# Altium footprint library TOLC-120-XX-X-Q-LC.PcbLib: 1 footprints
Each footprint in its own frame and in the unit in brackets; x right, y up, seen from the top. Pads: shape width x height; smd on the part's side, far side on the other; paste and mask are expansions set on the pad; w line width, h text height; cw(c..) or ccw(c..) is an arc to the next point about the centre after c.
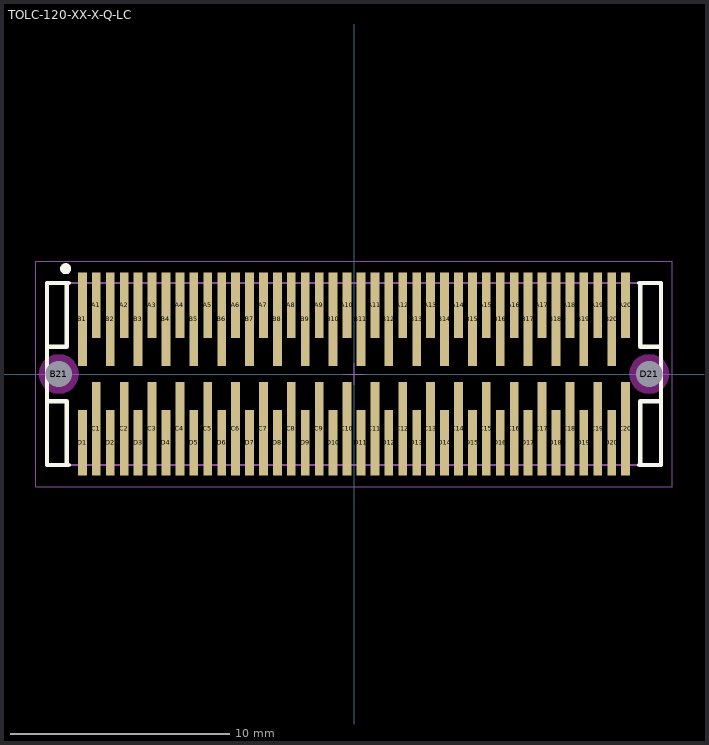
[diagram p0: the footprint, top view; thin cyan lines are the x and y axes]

## TOLC-120-XX-X-Q-LC [mm] "1.27mm pitch, 80 pin, terminal strip; 4 rows, w/locking clips, SMT"
height 5.59
pads (82):
  rect 0.4x3 smd mask+0: A1(-11.747,3.135) A2(-10.477,3.135) A3(-9.207,3.135) A4(-7.938,3.135) A5(-6.667,3.135) A6(-5.397,3.135) A7(-4.127,3.135) A8(-2.857,3.135) A9(-1.587,3.135) A10(-0.318,3.135) A11(0.953,3.135) A12(2.222,3.135) A13(3.492,3.135) A14(4.763,3.135) A15(6.032,3.135) A16(7.302,3.135) A17(8.572,3.135) A18(9.842,3.135) A19(11.112,3.135) A20(12.383,3.135) D1(-12.383,-3.135) D2(-11.112,-3.135) D3(-9.842,-3.135) D4(-8.572,-3.135) D5(-7.302,-3.135) D6(-6.032,-3.135) D7(-4.763,-3.135) D8(-3.492,-3.135) D9(-2.222,-3.135) D10(-0.953,-3.135) D11(0.318,-3.135) D12(1.587,-3.135) D13(2.857,-3.135) D14(4.127,-3.135) D15(5.397,-3.135) D16(6.667,-3.135) D17(7.938,-3.135) D18(9.207,-3.135) D19(10.477,-3.135) D20(11.747,-3.135)
  rect 0.4x4.25 smd mask+0: B1(-12.383,2.5) B2(-11.112,2.5) B3(-9.842,2.5) B4(-8.572,2.5) B5(-7.302,2.5) B6(-6.032,2.5) B7(-4.763,2.5) B8(-3.492,2.5) B9(-2.222,2.5) B10(-0.953,2.5) B11(0.318,2.5) B12(1.587,2.5) B13(2.857,2.5) B14(4.127,2.5) B15(5.397,2.5) B16(6.667,2.5) B17(7.938,2.5) B18(9.207,2.5) B19(10.477,2.5) B20(11.747,2.5) C1(-11.747,-2.5) C2(-10.477,-2.5) C3(-9.207,-2.5) C4(-7.938,-2.5) C5(-6.667,-2.5) C6(-5.397,-2.5) C7(-4.127,-2.5) C8(-2.857,-2.5) C9(-1.587,-2.5) C10(-0.318,-2.5) C11(0.953,-2.5) C12(2.222,-2.5) C13(3.492,-2.5) C14(4.763,-2.5) C15(6.032,-2.5) C16(7.302,-2.5) C17(8.572,-2.5) C18(9.842,-2.5) C19(11.112,-2.5) C20(12.383,-2.5)
  round 1 hole 1.2 unplated mask+0: B21(-13.462,0) D21(13.462,0)
Top Overlay:
  circle w0.25: c-13.15,4.8 r0.125
  lines w0.2: -14,-1.25 -13.1,-1.25 -13.1,-4.15 ; -14,1.25 -13.1,1.25 -13.1,4.15 ; -13,-4.15 -14,-4.15 -14,4.15 -13,4.15 ; 13,-4.15 14,-4.15 14,4.15 13,4.15 ; 13.05,-4.15 13.05,-1.25 13.95,-1.25 ; 13.05,4.15 13.05,1.25 13.95,1.25
Keep-Out Layer:
  pour cut-out: -12.554,0 -12.585,0.235 -12.676,0.454 -12.82,0.642 -13.008,0.786 -13.227,0.877 -13.462,0.908 -13.697,0.877 -13.916,0.786 -14.104,0.642 -14.248,0.454 -14.339,0.235 -14.37,0 -14.339,-0.235 -14.248,-0.454 -14.104,-0.642 -13.916,-0.786 -13.697,-0.877 -13.462,-0.908 -13.227,-0.877 -13.008,-0.786 -12.82,-0.642 -12.676,-0.454 -12.585,-0.235
  pour cut-out: 14.37,0 14.339,0.235 14.248,0.454 14.104,0.642 13.916,0.786 13.697,0.877 13.462,0.908 13.227,0.877 13.008,0.786 12.82,0.642 12.676,0.454 12.585,0.235 12.554,0 12.585,-0.235 12.676,-0.454 12.82,-0.642 13.008,-0.786 13.227,-0.877 13.462,-0.908 13.697,-0.877 13.916,-0.786 14.104,-0.642 14.248,-0.454 14.339,-0.235
Mechanical 12:
  lines w0.001: -14,-4.15 14,-4.15 14,4.15 -14,4.15 -14,-4.15 ; -14,-1.25 -14,1.25 -13.1,1.25 -13.1,4.15 13.05,4.15 13.05,1.25 14,1.25 14,-1.25 13.05,-1.25 13.05,-4.15 -13.1,-4.15 -13.1,-1.25 -14,-1.25
Mechanical 13:
  circle w0.1: c-12.399,3.265 r0.127
  lines w0.1: -14,-4.15 14,-4.15 14,4.15 -14,4.15 -14,-4.15 ; -14,-1.25 -14,1.25 -13.1,1.25 -13.1,4.15 13.05,4.15 13.05,1.25 14,1.25 14,-1.25 13.05,-1.25 13.05,-4.15 -13.1,-4.15 -13.1,-1.25 -14,-1.25
  text ".Designator" at 0,-0.127 h1.52
Mechanical 15:
  lines w0.05: -0.5,0 0.5,0 ; 0,-0.5 0,0.5 ; -14.5,-5.15 -14.5,5.15 14.5,5.15 14.5,-5.15 -14.5,-5.15
Mechanical 16:
  circle w0.001: c-12.399,3.265 r0.127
